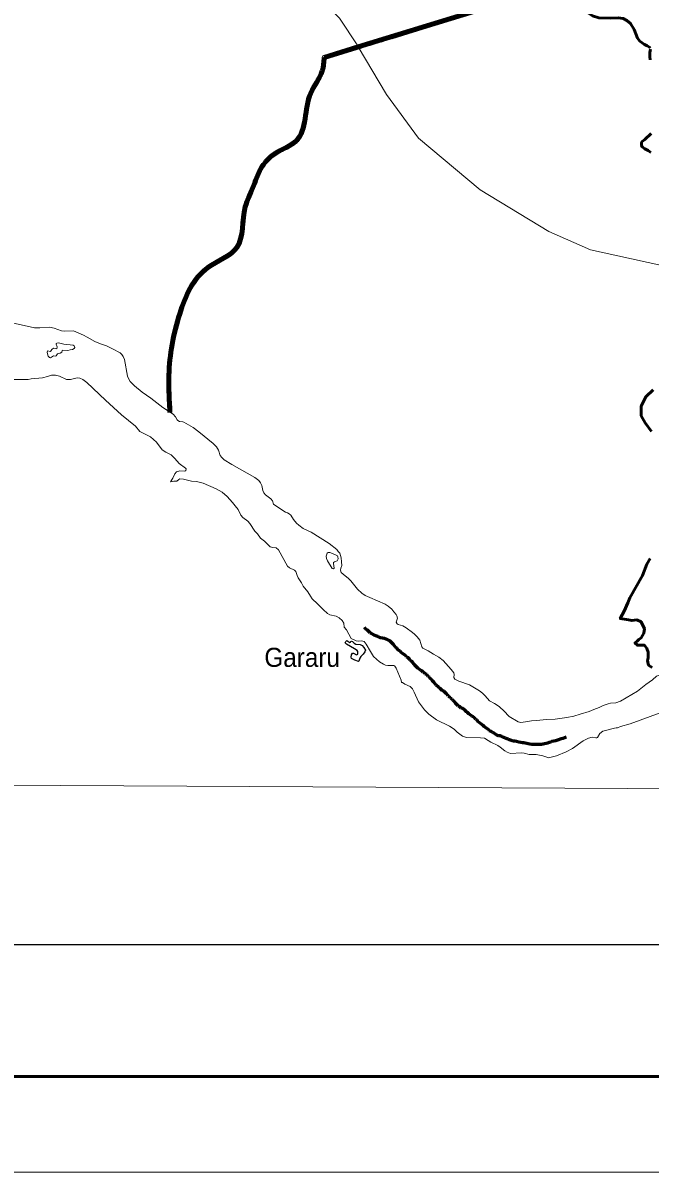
# Model space of a CAD drawing. Extents: x 553962 to 842807, y 8883888 to 9032388.
# Drawn here: x 701363 to 717768, y 8883888 to 8913971 of the extents above; entities that cross this region are included whole.
import ezdxf

# ---------------------------------------------------------------- set-up
doc = ezdxf.new("R2010")
doc.units = 0
doc.header["$LTSCALE"] = 200
doc.header["$PDMODE"] = 32
doc.header["$PDSIZE"] = 100
doc.linetypes.add('DASH_DOUBLE_DOT', pattern=[9.2, 5, -1.2, 0.3, -1.2, 0.3, -1.2])
doc.linetypes.add('LONG_DASH_SHORT_DASH', pattern=[9.9, 6, -1.2, 1.5, -1.2])
for name, color, linetype, lineweight in [('1', 7, 'Continuous', 13), ('11', 7, 'DASH_DOUBLE_DOT', 106), ('21', 7, 'Continuous', 25), ('24', 7, 'Continuous', 25), ('25', 7, 'Continuous', 13), ('3', 7, 'Continuous', 13), ('41', 7, 'Continuous', 40), ('57', 7, 'Continuous', 13), ('7', 7, 'LONG_DASH_SHORT_DASH', 60), ('9', 7, 'Continuous', 90)]:
    doc.layers.add(name, color=color, linetype=linetype, lineweight=lineweight)

msp = doc.modelspace()

# ---------------------------------------------------------------- linework, layer by layer
at = {"layer": '1'}
msp.add_lwpolyline([(564751.7, 8894587.5), (664411.9, 8894209.9), (791388.5, 8893536.2)], dxfattribs=at)
at = {"layer": '11'}
msp.add_line((709242.2, 8913071.2), (715561.4, 8915010.8), dxfattribs=at)
msp.add_spline([(705207.9, 8903769.6), (705180.7, 8904747.4), (705463.8, 8906360), (706198.7, 8907564.6), (706955.5, 8908091.1), (707178.8, 8909156.3), (707379.5, 8909664.2), (707580.3, 8910146.8), (707959.3, 8910554.8), (708516.4, 8910888.1), (708891.3, 8912131.7), (709193.2, 8912716.3), (709242.2, 8913071.2)], degree=3, dxfattribs=at)
at = {"layer": '21'}
msp.add_lwpolyline([(710323, 8897547.4), (710310.6, 8897510.9), (710262.7, 8897448.5), (710205.4, 8897388.1), (710179.6, 8897340.9), (710149.4, 8897265.1), (710140.8, 8897256.9), (710043.9, 8897288.4), (709961.7, 8897329.1), (709947.6, 8897363.1), (709961.6, 8897429.2), (709984.2, 8897470), (709989.6, 8897472.6), (710012.7, 8897467.5), (710090.3, 8897425.2), (710122.4, 8897447.6), (710126, 8897519.8), (710103.3, 8897545.3), (710035.6, 8897588.8), (709826.1, 8897706.4), (709795.6, 8897744), (709810.8, 8897781.5), (709838, 8897800.1), (709914.9, 8897754.6), (709934.2, 8897760.9), (709942.3, 8897776.2), (709957.1, 8897785.6), (709980.8, 8897774.5), (710029.3, 8897733.8), (710072, 8897710.7), (710184.3, 8897701.5), (710239.2, 8897671.8), (710278.2, 8897623.4), (710322, 8897552.2)], close=True, dxfattribs=at)
at = {"layer": '24', "lineweight": 53}
for points in [[(715582.8, 8914999.5), (715607.3, 8914926.5), (715630.8, 8914782.1), (715664.2, 8914698.4), (715720.4, 8914621.3), (715841.4, 8914484.8), (715976.3, 8914382.9), (716121.9, 8914251.7), (716262.7, 8914158.2), (716430.6, 8914102.4), (716723.3, 8914098.2), (716931, 8914106.3), (717067.3, 8914089.8), (717160, 8914040), (717258.6, 8913960.8), (717350.2, 8913798.9), (717444.9, 8913569.6), (717500.7, 8913495.3), (717620.4, 8913403.7), (717696.9, 8913374.6), (717753.4, 8913338.3), (717771.3, 8913315.3)], [(717779.7, 8913284.7), (717767.4, 8913198.7), (717765.2, 8913088.6), (717776, 8913003.3)], [(717799.8, 8911079.5), (717637.2, 8910919.9), (717559.9, 8910863.9), (717548.7, 8910844.9), (717546.6, 8910765.8), (717564.2, 8910723.9), (717629.5, 8910673.2), (717717.9, 8910632.5), (717786.1, 8910583.9)], [(717854.7, 8904369.6), (717655.3, 8904186.9), (717539, 8903937.8), (717539, 8903688.8), (717638.7, 8903506.1), (717804.9, 8903273.6)], [(717771.7, 8899952.6), (717688.6, 8899803.1), (717572.3, 8899504.2), (717240, 8898923), (717190.1, 8898790.2), (717090.4, 8898574.3), (716990.8, 8898375.1), (717206.8, 8898341.9), (717289.8, 8898325.2), (717422.7, 8898341.9), (717539, 8898292), (717622.1, 8898109.4), (717605.5, 8897993.1), (717539, 8897876.9), (717472.6, 8897827.1), (717422.7, 8897777.3), (717372.9, 8897744.1), (717439.4, 8897677.6), (717622.1, 8897677.6), (717688.6, 8897594.6), (717721.8, 8897495), (717721.8, 8897395.3), (717721.8, 8897345.5), (717705.2, 8897279.1), (717721.8, 8897196.1), (717738.4, 8897146.3), (717821.5, 8897096.4)]]:
    msp.add_lwpolyline(points, dxfattribs=at)
at = {"layer": '25'}
for points in [[(699730.1, 8905870.1), (699833.6, 8905937.4), (700049.1, 8906011), (700564.9, 8906093.9), (701005.2, 8906113.6), (701154.5, 8906101.4), (701659.8, 8905992.8), (701803.5, 8905986.5), (702058.9, 8906003.4), (702175.9, 8905983.8), (702373, 8905910.6), (702436.8, 8905905.5), (702682, 8905912.8), (702942.6, 8905799.8), (703043.5, 8905742.3)], [(703043.5, 8905742.3), (703240.1, 8905630.3), (703386.8, 8905567), (703544.9, 8905514.5)], [(703544.9, 8905514.5), (703544.9, 8905514.5), (703708.6, 8905443.2), (703903.3, 8905333.4), (703950.4, 8905293.2), (703983.7, 8905242.4), (704017.5, 8905157.8), (704100.5, 8904727.4), (704116.7, 8904678.1), (704169.6, 8904585.4), (704276.9, 8904471.4), (704483.1, 8904302.2), (704709.8, 8904149.5), (705025.3, 8903904.5), (705294.1, 8903731.4), (705355.9, 8903661.9), (705397.8, 8903579.9), (705416.3, 8903559.4), (705456.6, 8903537.1), (705545.2, 8903528.8), (705574.6, 8903518.8), (705812.1, 8903380.7), (705964.1, 8903265.1), (706335.8, 8902958.3), (706429, 8902870.5), (706478.4, 8902782.6), (706522.3, 8902644.6), (706561.4, 8902592.6), (706627.5, 8902537.3), (706829.4, 8902410.4), (707426.7, 8902069.6), (707536.7, 8901989.7), (707580.8, 8901930.1), (707613.5, 8901857.8), (707638, 8901734), (707661.4, 8901666.3), (707707.1, 8901616.1), (707849, 8901513.6), (707889.3, 8901456.4), (707921.2, 8901374.1), (708164.6, 8901203.2), (708234, 8901164.4), (708282.6, 8901144)], [(701498, 8904635.9), (701073.3, 8904639.9), (700893.6, 8904612.2), (700683.7, 8904613.8), (700499, 8904578.5), (700435.5, 8904574.2), (700368.5, 8904593.8)], [(702004.3, 8904719), (701870.4, 8904678.1), (701577.9, 8904651), (701498, 8904635.9)], [(703520.5, 8904092.8), (703035.9, 8904557.4), (702930.4, 8904637.9), (702854, 8904670.9), (702784.7, 8904678.3), (702603.6, 8904639.4), (702499.6, 8904635.8), (702318.3, 8904724.9), (702212.1, 8904749.4), (702106.6, 8904750.3), (702004.3, 8904719)], [(704418.9, 8903273.5), (704303.8, 8903412.4), (703938.7, 8903713.3), (703520.5, 8904092.8)], [(705417, 8902230.5), (705468.7, 8902243.1), (705601.7, 8902236.3), (705626.1, 8902249.9), (705630.1, 8902294), (705613.1, 8902318.7), (705450.5, 8902433.4), (705338.6, 8902571.8), (705237.8, 8902662.7), (705098.5, 8902732.8), (705008.4, 8902794.2), (704859.8, 8902995.3), (704700.7, 8903136.3), (704418.9, 8903273.5)], [(705223.5, 8901956.6), (705285.9, 8902055.5), (705327.2, 8902145.4), (705340, 8902163.9), (705340, 8902163.9)], [(705340, 8902163.9), (705380.2, 8902221.5), (705417, 8902230.5)], [(706917, 8901328.8), (706845.7, 8901419), (706706.3, 8901570.6), (706577.5, 8901683.7), (706418, 8901776), (706077.6, 8901924.8), (705902.1, 8901964.8), (705769.4, 8901975.3), (705559.8, 8902024.1), (705462.6, 8902034.1), (705436.9, 8902022.7), (705383.9, 8901976.1), (705305.7, 8901975.9), (705223.5, 8901956.6)], [(708884.8, 8898960.2), (708812.9, 8899081.1), (708692, 8899230.3), (708649.9, 8899313.3), (708562.2, 8899440.2), (708534.2, 8899502.9), (708503.8, 8899608.4), (708465.9, 8899644.1), (708336.8, 8899710.3), (708284.4, 8899750.1), (708047.8, 8900175.7), (707990.8, 8900226.5), (707897.1, 8900236.8), (707831, 8900260), (707784.3, 8900295.7), (707679.2, 8900403.7), (707579.3, 8900485.4), (707498.4, 8900600.3), (707426.9, 8900668.2), (707296.2, 8900870.2), (707244.9, 8900923.6), (707114.9, 8901025.9), (707060.8, 8901088.8), (706991.1, 8901234.8), (706917, 8901328.8)], [(708282.6, 8901144), (708331.2, 8901123.5), (708369.6, 8901088.6), (708444.9, 8900971.6), (708520.8, 8900871.2), (708577.2, 8900819.4), (708690.2, 8900735.5), (708901.9, 8900638.8), (709137.2, 8900490.7)], [(709137.2, 8900490.7), (709372.6, 8900342.6), (709571.9, 8900187.3), (709610.7, 8900136.5)], [(709610.7, 8900136.5), (709649.5, 8900085.8), (709687.8, 8899966.6), (709696.9, 8899867.4)], [(709696.9, 8899867.4), (709706, 8899768.3), (709680, 8899695), (709673.6, 8899642.5), (709691.5, 8899588), (709738.8, 8899535.9), (709875.6, 8899429.5), (709875.6, 8899429.5), (709939.8, 8899367.7), (710112.9, 8899145), (710229.9, 8899043.2), (710316.3, 8898983), (710434.5, 8898930.1)], [(709950.2, 8897853.8), (709826.5, 8898078.7), (709765, 8898154.3), (709755.6, 8898257.5), (709714.4, 8898328.8), (709634.6, 8898396.5), (709559.8, 8898439.4), (709395, 8898473.4), (709333.8, 8898506.8), (709214.9, 8898614.3), (709070.8, 8898765.5), (708925, 8898892.5), (708884.8, 8898960.2)], [(710434.5, 8898930.1), (710835, 8898750.5), (710918.4, 8898699.6), (711013.8, 8898623.8), (711070, 8898553.2)], [(711070, 8898553.2), (711126.2, 8898482.6), (711144.3, 8898448), (711158.3, 8898389.2), (711130.3, 8898282.3), (711152.8, 8898240), (711175.8, 8898222.2), (711302.1, 8898183.8), (711391.3, 8898138.3), (711554.3, 8898011), (711603.7, 8897966)], [(711603.7, 8897966), (711680.2, 8897896.3), (711746, 8897808.5), (711799.4, 8897633.4), (711822.1, 8897601.2), (711960, 8897533.9), (712103.8, 8897448.7)], [(710692.4, 8897249.1), (710533.9, 8897388.5), (710451.3, 8897511.8), (710342.9, 8897708), (710286.4, 8897777.2), (710220.4, 8897794.9), (710145.3, 8897789.3), (710079.5, 8897794.7), (709950.2, 8897853.8)], [(712103.8, 8897448.7), (712242.6, 8897366.3), (712359.3, 8897283.4), (712565.7, 8897048.4), (712631.8, 8896958.1), (712647.9, 8896909.4), (712637.9, 8896831.9), (712665.2, 8896790.9), (712768.3, 8896741.4), (713044.9, 8896638.8), (713311.2, 8896489.3), (713385.5, 8896424.1)], [(711124.5, 8897078.8), (711093, 8897127.9), (711068.7, 8897147.8), (711049.5, 8897152.8), (710908.8, 8897146.9), (710849.4, 8897155.7), (710797.6, 8897180.7), (710692.4, 8897249.1)], [(712525.7, 8895564.3), (712179.3, 8895726.8), (711977.5, 8895873.7), (711872.3, 8895986), (711707.5, 8896200.3), (711600.3, 8896454.3), (711553.8, 8896536.9), (711494.9, 8896598.8), (711354.3, 8896661.8), (711292.1, 8896701.3), (711270.5, 8896704.9), (711261.3, 8896763.5), (711124.5, 8897078.8)], [(716671.9, 8896141.4), (716736, 8896160), (716876.8, 8896172.9), (716996.8, 8896216.3), (717443.2, 8896481.3), (717658.9, 8896651.8), (717833.2, 8896772.8), (717934, 8896865.6), (718070.7, 8896913.8), (718220.3, 8896913.8), (718619, 8896913.8), (718918.1, 8896963.6), (719252.2, 8897020.3)], [(713385.5, 8896424.1), (713459.8, 8896359), (713569.8, 8896225.6), (713696.9, 8896155.1), (713818.3, 8896075.1), (713842, 8896053.8)], [(715944.9, 8895871), (716177.3, 8895944.3), (716297, 8895998.6), (716434.9, 8896046.3), (716544.4, 8896104.3), (716671.9, 8896141.4)], [(713842, 8896053.8), (713946.1, 8895960.1), (714080.1, 8895815.7), (714321.1, 8895672.2), (714384.5, 8895659.7), (714451.9, 8895662.4), (714514.6, 8895674.6)], [(715407.8, 8895761.9), (715591.5, 8895783.2), (715777.5, 8895818.2), (715944.9, 8895871)], [(719242.1, 8895974.6), (719137.8, 8895926.7), (719051.9, 8895910.8), (718819, 8895950.7), (718570.6, 8895982.3), (718406.7, 8895992.1), (718284.1, 8895976.8), (718038.4, 8895905.8), (717250.7, 8895623.3), (716998.4, 8895554.6), (716915, 8895518.1), (716881.8, 8895513.8)], [(713532.7, 8895186.2), (713435.1, 8895242.8), (713335.4, 8895258.7), (712968.6, 8895262), (712859.7, 8895301.9), (712725.3, 8895401.6), (712648.5, 8895483.1), (712525.7, 8895564.3)], [(714514.6, 8895674.6), (714664.7, 8895703.8), (714810.4, 8895708.8), (715055.3, 8895739.1), (715289.1, 8895748.2), (715407.8, 8895761.9)], [(716881.8, 8895513.8), (716841.2, 8895508.6), (716533, 8895427), (716458.2, 8895365.9), (716394.5, 8895260), (716374.9, 8895256.9)], [(716374.9, 8895256.9), (716350.2, 8895253.1), (716257.5, 8895274.6), (716162.3, 8895243), (716023.3, 8895172.8), (715744.1, 8894976.4), (715570.5, 8894886.6), (715322, 8894784.1), (715114.6, 8894733.5), (715039.1, 8894760)], [(715039.1, 8894760), (714963.6, 8894786.5), (714790.6, 8894820), (714606.1, 8894818.8), (714473.2, 8894853.3), (714404.1, 8894859.6), (714116.9, 8894843.6), (714034.5, 8894876.8), (713967, 8894916.7), (713850.5, 8895013.2), (713789.1, 8895053.9), (713604, 8895144.8), (713532.7, 8895186.2)]]:
    msp.add_lwpolyline(points, dxfattribs=at)
for points in [[(702679.3, 8905532.6), (702433.7, 8905559), (702292.5, 8905598.5), (702244.4, 8905591.1), (702234.6, 8905581.9), (702232, 8905562.8), (702259.6, 8905493.7), (702249.4, 8905443.2), (702159.4, 8905461.2), (702115.8, 8905419.6), (702084.4, 8905369.4), (702001, 8905388), (701998, 8905341.8), (702023.2, 8905250.2), (702057, 8905211), (702086.6, 8905207.7), (702162.1, 8905255.6), (702214.5, 8905249.9), (702235, 8905255.7), (702269.6, 8905309.9), (702336.8, 8905325.8), (702376.9, 8905350), (702388.8, 8905392.2), (702403.4, 8905405.1), (702532.1, 8905397.2), (702600.3, 8905416.2), (702662.5, 8905423.3), (702700.1, 8905446), (702715.3, 8905477.1), (702706.1, 8905515.4)], [(709580.3, 8899889.8), (709596.2, 8899906.3), (709606, 8899943.5), (709599.7, 8899997.3), (709588.6, 8900017.3), (709459.5, 8900083.7), (709393.7, 8900104.9), (709351.6, 8900105.7), (709323, 8900086.1), (709294.9, 8900014.3), (709301.9, 8899949.1), (709327.1, 8899890.5), (709454.5, 8899688.2), (709485.7, 8899677.3), (709503.8, 8899701.2), (709483.4, 8899821.2), (709487.6, 8899841.5), (709510.1, 8899860.5)]]:
    msp.add_lwpolyline(points, close=True, dxfattribs=at)
at = {"layer": '3'}
msp.add_lwpolyline([(842807.3, 9032387.8), (842807.3, 8883887.8), (553961.7, 8883887.8), (553961.7, 9032387.8)], close=True, dxfattribs=at)
at = {"layer": '3', "lineweight": 53}
msp.add_lwpolyline([(840307.3, 9029887.8), (840307.3, 8886387.8), (560211.7, 8886387.8), (560211.7, 9029887.8)], close=True, dxfattribs=at)
at = {"layer": '3', "lineweight": 25}
msp.add_lwpolyline([(563033.9, 9026438.8), (793061.1, 9026438.8), (793495.6, 8889836.8), (563468.3, 8889836.8)], close=True, dxfattribs=at)
at = {"layer": '57'}
for points in [[(710120.3, 8913369), (709646.4, 8914096), (708983, 8914759.8), (708256.3, 8915202.3), (707118.9, 8915708.1), (706297.5, 8916055.8), (702263.2, 8917164.2)], [(725327.2, 8906726.4), (724297.2, 8906891.3), (722767.2, 8907153.7), (720450.5, 8907416.1), (718789.4, 8907459.9), (716210.4, 8908028.4), (715117.6, 8908509.5), (713325.3, 8909602.9), (711708, 8910958.7), (710877.4, 8912095.8), (710134.6, 8913345.1), (709242.2, 8913071.2)], [(699730.1, 8905870.1), (699833.6, 8905937.4), (700049.1, 8906011), (700564.9, 8906093.9), (701005.2, 8906113.6), (701154.5, 8906101.4), (701659.8, 8905992.8), (701803.5, 8905986.5), (702058.9, 8906003.4), (702175.9, 8905983.8), (702373, 8905910.6), (702436.8, 8905905.5), (702682, 8905912.8), (702942.6, 8905799.8), (703043.5, 8905742.3)], [(703043.5, 8905742.3), (703240.1, 8905630.3), (703386.8, 8905567), (703544.9, 8905514.5)], [(703544.9, 8905514.5), (703708.6, 8905443.2), (703903.3, 8905333.4), (703950.4, 8905293.2), (703983.7, 8905242.4), (704017.5, 8905157.8), (704100.5, 8904727.4), (704116.7, 8904678.1), (704169.6, 8904585.4), (704276.9, 8904471.4), (704483.1, 8904302.2), (704709.8, 8904149.5), (705025.3, 8903904.5), (705207.4, 8903787.2)], [(705207.6, 8903781.6), (705215.8, 8903781.8), (705294.1, 8903731.4)], [(705294.1, 8903731.4), (705355.9, 8903661.9), (705397.8, 8903579.9), (705416.3, 8903559.4), (705456.6, 8903537.1), (705545.2, 8903528.8), (705574.6, 8903518.8), (705812.1, 8903380.7), (705964.1, 8903265.1), (706335.8, 8902958.3), (706429, 8902870.5), (706478.4, 8902782.6), (706522.3, 8902644.6), (706561.4, 8902592.6), (706627.5, 8902537.3), (706829.4, 8902410.4), (707426.7, 8902069.6), (707536.7, 8901989.7), (707580.8, 8901930.1), (707613.5, 8901857.8), (707638, 8901734), (707661.4, 8901666.3), (707707.1, 8901616.1), (707849, 8901513.6), (707889.3, 8901456.4), (707921.2, 8901374.1), (708164.6, 8901203.2), (708234, 8901164.4), (708282.6, 8901144)], [(708282.6, 8901144), (708331.2, 8901123.5), (708369.6, 8901088.6), (708444.9, 8900971.6), (708520.8, 8900871.2), (708577.2, 8900819.4), (708690.2, 8900735.5), (708901.9, 8900638.8), (709137.2, 8900490.7)], [(709137.2, 8900490.7), (709372.6, 8900342.6), (709571.9, 8900187.3), (709610.7, 8900136.5)], [(709610.7, 8900136.5), (709649.5, 8900085.8), (709687.8, 8899966.6), (709696.9, 8899867.4)], [(709696.9, 8899867.4), (709706, 8899768.3), (709680, 8899695), (709673.6, 8899642.5), (709691.5, 8899588), (709738.8, 8899535.9), (709875.6, 8899429.5), (709875.6, 8899429.5), (709939.8, 8899367.7), (710112.9, 8899145), (710229.9, 8899043.2), (710316.3, 8898983), (710434.5, 8898930.1)], [(710434.5, 8898930.1), (710835, 8898750.5), (710918.4, 8898699.6), (711013.8, 8898623.8), (711070, 8898553.2)], [(711070, 8898553.2), (711126.2, 8898482.6), (711144.3, 8898448), (711158.3, 8898389.2), (711130.3, 8898282.3), (711152.8, 8898240), (711175.8, 8898222.2), (711302.1, 8898183.8), (711391.3, 8898138.3), (711554.3, 8898011), (711603.7, 8897966)], [(711603.7, 8897966), (711680.2, 8897896.3), (711746, 8897808.5), (711799.4, 8897633.4), (711822.1, 8897601.2), (711960, 8897533.9), (712103.8, 8897448.7)], [(712103.8, 8897448.7), (712242.6, 8897366.3), (712359.3, 8897283.4), (712565.7, 8897048.4), (712631.8, 8896958.1), (712647.9, 8896909.4), (712637.9, 8896831.9), (712665.2, 8896790.9), (712768.3, 8896741.4), (713044.9, 8896638.8), (713311.2, 8896489.3), (713385.5, 8896424.1)], [(716671.9, 8896141.4), (716736, 8896160), (716876.8, 8896172.9), (716996.8, 8896216.3), (717443.2, 8896481.3), (717658.9, 8896651.8), (717833.2, 8896772.8), (717934, 8896865.6), (718070.7, 8896913.8), (718220.3, 8896913.8), (718619, 8896913.8), (718918.1, 8896963.6), (719252.2, 8897020.3)], [(713385.5, 8896424.1), (713459.8, 8896359), (713569.8, 8896225.6), (713696.9, 8896155.1), (713818.3, 8896075.1), (713842, 8896053.8)], [(715944.9, 8895871), (716177.3, 8895944.3), (716297, 8895998.6), (716434.9, 8896046.3), (716544.4, 8896104.3), (716671.9, 8896141.4)], [(713842, 8896053.8), (713946.1, 8895960.1), (714080.1, 8895815.7), (714321.1, 8895672.2), (714384.5, 8895659.7), (714451.9, 8895662.4), (714514.6, 8895674.6)], [(715407.8, 8895761.9), (715591.5, 8895783.2), (715777.5, 8895818.2), (715944.9, 8895871)], [(714514.6, 8895674.6), (714664.7, 8895703.8), (714810.4, 8895708.8), (715055.3, 8895739.1), (715289.1, 8895748.2), (715407.8, 8895761.9)]]:
    msp.add_lwpolyline(points, dxfattribs=at)
for points in [[(709242.2, 8913071.2), (709193.2, 8912716.3), (708891.3, 8912131.7), (708516.4, 8910888.1), (707959.3, 8910554.8), (707580.3, 8910146.8), (707379.5, 8909664.2), (707178.8, 8909156.3), (706955.5, 8908091.1), (706198.7, 8907564.6), (705463.8, 8906360), (705180.7, 8904747.4), (705207.6, 8903781.6)], [(705207.4, 8903787.2), (705180.7, 8904747.4), (705463.8, 8906360), (706198.7, 8907564.6), (706955.5, 8908091.1), (707178.8, 8909156.3), (707379.5, 8909664.2), (707580.3, 8910146.8), (707959.3, 8910554.8), (708516.4, 8910888.1), (708891.3, 8912131.7), (709193.2, 8912716.3), (709242.2, 8913071.2)]]:
    msp.add_spline(points, degree=3, dxfattribs=at)
for p in [(710131.8, 8913344.2), (709242.2, 8913071.2)]:
    msp.add_point(p, dxfattribs=at)
at = {"layer": '7'}
for points in [[(711474.4, 8897314.1), (711433.6, 8897355), (711398, 8897378), (711370, 8897413.8), (711308.9, 8897454.7), (711270.7, 8897477.7), (711230, 8897521.1), (711189.3, 8897549.2), (711148.6, 8897600.3), (711112.9, 8897631), (711056.9, 8897694.9), (711016.2, 8897746.1), (710965.3, 8897792.1), (710911.8, 8897817.6), (710817.7, 8897856), (710718.5, 8897873.8), (710647.2, 8897904.5), (710598.8, 8897925), (710555.6, 8897945.4), (710507.2, 8897965.9), (710481.8, 8897986.3), (710448.7, 8898001.7), (710413.1, 8898034.9), (710374.9, 8898073.2), (710334.2, 8898098.8), (710296.3, 8898144.4)], [(712701.2, 8896140.8), (712675.8, 8896166.4), (712632.5, 8896220.1), (712599.4, 8896243.1), (712581.6, 8896276.3), (712546, 8896294.2), (712525.6, 8896327.4), (712487.4, 8896347.9), (712467.1, 8896388.8), (712431.4, 8896414.3), (712375.4, 8896475.7), (712327.1, 8896498.7), (712276.2, 8896547.2), (712230.3, 8896585.6), (712176.9, 8896636.7), (712146.3, 8896664.8), (712110.7, 8896708.3), (712075.1, 8896746.6), (712052.2, 8896784.9), (712016.5, 8896805.4), (711996.2, 8896843.7), (711960.5, 8896861.6), (711924.9, 8896910.2), (711889.3, 8896928.1), (711866.3, 8896958.8), (711830.7, 8896976.7), (711795.1, 8897009.9), (711759.5, 8897027.8), (711718.7, 8897061), (711695.8, 8897081.5), (711657.6, 8897112.1), (711619.5, 8897158.2), (711594, 8897186.3), (711555.8, 8897232.3), (711532.9, 8897257.8), (711497.3, 8897291.1), (711474.4, 8897314.1)], [(715172.3, 8895138.8), (715134.1, 8895136.3), (715085.8, 8895115.8), (715047.6, 8895103.1), (715004.4, 8895095.4), (714963.7, 8895087.7), (714935.7, 8895082.6), (714900.1, 8895077.5), (714841.5, 8895077.5), (714803.3, 8895077.5), (714762.7, 8895077.5), (714739.7, 8895077.5), (714701.6, 8895080), (714673.6, 8895082.6), (714625.2, 8895090.3), (714582, 8895097.9), (714541.3, 8895105.6), (714503.1, 8895113.3), (714464.9, 8895120.9), (714431.8, 8895128.6), (714391.1, 8895136.3), (714332.6, 8895143.9), (714279.2, 8895159.3), (714230.8, 8895166.9), (714185, 8895166.9), (714144.3, 8895187.4), (714096, 8895205.3), (714055.2, 8895220.6), (714034.9, 8895225.7), (714004.3, 8895241.1), (713984, 8895246.2), (713945.8, 8895264.1), (713922.9, 8895269.2), (713889.8, 8895289.6), (713851.6, 8895307.5), (713808.4, 8895310.1), (713762.6, 8895328), (713732, 8895345.9), (713693.9, 8895376.5), (713653.1, 8895391.9), (713612.4, 8895425.1), (713569.2, 8895440.4), (713541.2, 8895471.1), (713503, 8895496.7), (713467.3, 8895527.3), (713429.2, 8895547.8), (713403.7, 8895581), (713370.6, 8895601.5), (713324.8, 8895642.4), (713273.9, 8895670.5), (713248.5, 8895716.5), (713210.3, 8895739.5), (713177.2, 8895775.3), (713131.4, 8895811.1), (713098.3, 8895831.5), (713057.6, 8895869.9), (713032.1, 8895885.2), (712991.4, 8895918.4), (712968.5, 8895933.8), (712930.3, 8895972.1), (712871.8, 8896020.7), (712828.5, 8896033.5), (712787.8, 8896074.3), (712747.1, 8896094.8), (712701.2, 8896140.8)], [(715575.1, 8895269.4), (715574.3, 8895269.2), (715533.6, 8895253.9), (715487.8, 8895238.5), (715444.5, 8895225.8), (715347.8, 8895195.1), (715294.4, 8895177.2), (715248.6, 8895164.4), (715200.3, 8895159.3), (715172.3, 8895138.8)]]:
    msp.add_lwpolyline(points, dxfattribs=at)
at = {"layer": '9'}
for p, q in [((710134.6, 8913345.1), (715561.4, 8915010.8)), ((709242.2, 8913071.2), (710135.7, 8913345.4))]:
    msp.add_line(p, q, dxfattribs=at)
msp.add_spline([(705207.9, 8903769.6), (705180.7, 8904747.4), (705463.8, 8906360), (706198.7, 8907564.6), (706955.5, 8908091.1), (707178.8, 8909156.3), (707379.5, 8909664.2), (707580.3, 8910146.8), (707959.3, 8910554.8), (708516.4, 8910888.1), (708891.3, 8912131.7), (709193.2, 8912716.3), (709242.2, 8913071.2)], degree=3, dxfattribs=at)

# ---------------------------------------------------------------- texts
at = {"layer": '41', "width": 0.95}
msp.add_text('Gararu', height=500, dxfattribs=at).set_placement((707678.8, 8897112.8))

doc.saveas('drawing.dxf')
